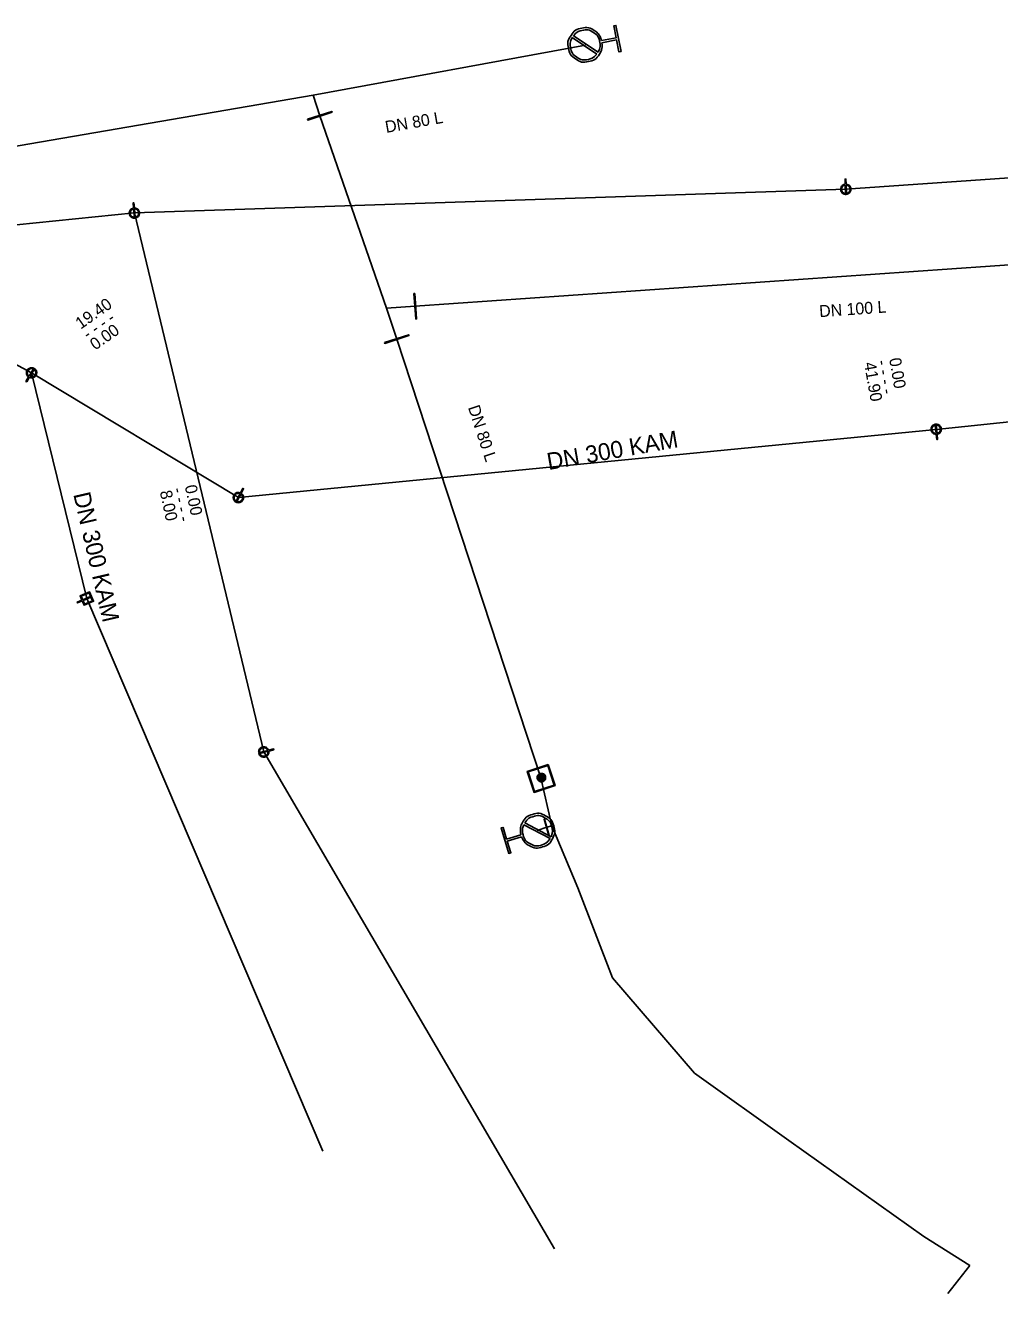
# Model space of a CAD drawing. Extents: x -818321 to -817653, y -1049725 to -1049329.
# Drawn here: x -817918.3 to -817861, y -1049467.6 to -1049393 of the extents above; entities that cross this region are included whole.
import ezdxf

# ---------------------------------------------------------------- set-up
doc = ezdxf.new("R2010")
doc.units = 0
doc.layers.add('Default', color=7, linetype='Continuous')
doc.layers.add('Level 0', color=7, linetype='Continuous')

msp = doc.modelspace()

# ---------------------------------------------------------------- linework, layer by layer
at = {"layer": 'Default'}
for points in [[(-817886.035, -1049393.634), (-817884.588, -1049394.608)], [(-817884.382, -1049393.921), (-817883.519, -1049393.754), (-817883.656, -1049393.048), (-817883.533, -1049393.024), (-817883.235, -1049394.558), (-817883.358, -1049394.582), (-817883.495, -1049393.876), (-817884.358, -1049394.044)], [(-817884.659, -1049394.714), (-817886.107, -1049393.737)], [(-817901.679, -1049398.548), (-817900.252, -1049398.085), (-817900.238, -1049398.129), (-817901.664, -1049398.593), (-817901.679, -1049398.548)], [(-817870.046, -1049402.367), (-817870.056, -1049402.066), (-817870.007, -1049402.065), (-817869.997, -1049402.365)], [(-817870.027, -1049402.915), (-817870.044, -1049402.418)], [(-817869.995, -1049402.416), (-817869.978, -1049402.913)], [(-817911.914, -1049403.77), (-817911.94, -1049403.471), (-817911.891, -1049403.466), (-817911.865, -1049403.766)], [(-817911.866, -1049404.316), (-817911.91, -1049403.821)], [(-817911.861, -1049403.817), (-817911.817, -1049404.312)], [(-817895.369, -1049408.795), (-817895.264, -1049410.291), (-817895.311, -1049410.294), (-817895.416, -1049408.798), (-817895.369, -1049408.795)], [(-817897.154, -1049411.687), (-817895.727, -1049411.223), (-817895.712, -1049411.268), (-817897.139, -1049411.731), (-817897.154, -1049411.687)], [(-817918.047, -1049413.732), (-817918.202, -1049413.99), (-817918.244, -1049413.964), (-817918.09, -1049413.707)], [(-817918.063, -1049413.663), (-817917.807, -1049413.236)], [(-817917.765, -1049413.262), (-817918.021, -1049413.688)], [(-817864.694, -1049417.033), (-817864.746, -1049416.539)], [(-817864.697, -1049416.534), (-817864.645, -1049417.028)], [(-817864.64, -1049417.079), (-817864.608, -1049417.378), (-817864.657, -1049417.383), (-817864.689, -1049417.084)], [(-817905.628, -1049420.524), (-817905.486, -1049420.258), (-817905.443, -1049420.281), (-817905.584, -1049420.547)], [(-817905.885, -1049421.008), (-817905.652, -1049420.569)], [(-817905.608, -1049420.592), (-817905.842, -1049421.031)], [(-817914.929, -1049426.879), (-817915.205, -1049426.996), (-817915.225, -1049426.951), (-817914.949, -1049426.834), (-817915.056, -1049426.58), (-817914.504, -1049426.346), (-817914.269, -1049426.898), (-817914.822, -1049427.133), (-817914.929, -1049426.879)], [(-817914.903, -1049426.815), (-817914.442, -1049426.619), (-817914.53, -1049426.41), (-817914.992, -1049426.606), (-817914.903, -1049426.815)], [(-817914.884, -1049426.86), (-817914.796, -1049427.068), (-817914.334, -1049426.872), (-817914.422, -1049426.664), (-817914.884, -1049426.86)], [(-817904.501, -1049435.803), (-817904.02, -1049435.674)], [(-817904.008, -1049435.722), (-817904.488, -1049435.851)], [(-817903.971, -1049435.661), (-817903.681, -1049435.583), (-817903.668, -1049435.631), (-817903.958, -1049435.709)], [(-817887.518, -1049436.507), (-817887.116, -1049437.743), (-817888.353, -1049438.145), (-817888.754, -1049436.908), (-817887.518, -1049436.507)], [(-817888.703, -1049436.934), (-817888.327, -1049438.094), (-817887.167, -1049437.717), (-817887.544, -1049436.558), (-817888.703, -1049436.934)], [(-817888.894, -1049439.931), (-817887.353, -1049440.751)], [(-817887.733, -1049439.709), (-817887.457, -1049440.67), (-817887.487, -1049440.679), (-817887.763, -1049439.718), (-817887.733, -1049439.709)], [(-817889.088, -1049440.748), (-817889.928, -1049441.005), (-817889.718, -1049441.692), (-817889.838, -1049441.729), (-817890.295, -1049440.235), (-817890.175, -1049440.198), (-817889.965, -1049440.886), (-817889.124, -1049440.629)], [(-817887.413, -1049440.861), (-817888.954, -1049440.043)]]:
    msp.add_lwpolyline(points, dxfattribs=at)
for points in [[(-817884.358, -1049394.044), (-817884.312, -1049394.431), (-817884.518, -1049394.734), (-817884.75, -1049395.076), (-817885.159, -1049395.155), (-817885.565, -1049395.234), (-817885.908, -1049395.002), (-817886.25, -1049394.77), (-817886.329, -1049394.362), (-817886.408, -1049393.957), (-817886.177, -1049393.614), (-817885.947, -1049393.271), (-817885.54, -1049393.192), (-817885.132, -1049393.112), (-817884.789, -1049393.342), (-817884.483, -1049393.545), (-817884.382, -1049393.921)], [(-817884.588, -1049394.608), (-817884.426, -1049394.33), (-817884.489, -1049394.004), (-817884.558, -1049393.647), (-817884.857, -1049393.446), (-817885.156, -1049393.244), (-817885.512, -1049393.314), (-817885.838, -1049393.377), (-817886.035, -1049393.634)], [(-817886.107, -1049393.737), (-817886.266, -1049394.013), (-817886.207, -1049394.338), (-817886.134, -1049394.692), (-817885.835, -1049394.894), (-817885.536, -1049395.097), (-817885.179, -1049395.028), (-817884.855, -1049394.965), (-817884.659, -1049394.714)], [(-817869.997, -1049402.365), (-817869.934, -1049402.367), (-817869.871, -1049402.4), (-817869.798, -1049402.437), (-817869.756, -1049402.507), (-817869.714, -1049402.577), (-817869.711, -1049402.655), (-817869.708, -1049402.733), (-817869.746, -1049402.807), (-817869.784, -1049402.88), (-817869.854, -1049402.921), (-817869.924, -1049402.962), (-817870, -1049402.965), (-817870.076, -1049402.968), (-817870.149, -1049402.932), (-817870.222, -1049402.895), (-817870.265, -1049402.825), (-817870.308, -1049402.754), (-817870.311, -1049402.676), (-817870.313, -1049402.598), (-817870.276, -1049402.525), (-817870.239, -1049402.452), (-817870.169, -1049402.41), (-817870.108, -1049402.373), (-817870.046, -1049402.367)], [(-817870.044, -1049402.418), (-817870.093, -1049402.423), (-817870.144, -1049402.454), (-817870.202, -1049402.488), (-817870.232, -1049402.549), (-817870.263, -1049402.609), (-817870.261, -1049402.674), (-817870.259, -1049402.739), (-817870.223, -1049402.798), (-817870.187, -1049402.857), (-817870.126, -1049402.887), (-817870.074, -1049402.913), (-817870.027, -1049402.915)], [(-817869.978, -1049402.913), (-817869.93, -1049402.907), (-817869.88, -1049402.878), (-817869.821, -1049402.844), (-817869.79, -1049402.783), (-817869.759, -1049402.721), (-817869.761, -1049402.656), (-817869.763, -1049402.591), (-817869.798, -1049402.533), (-817869.833, -1049402.475), (-817869.894, -1049402.445), (-817869.946, -1049402.418), (-817869.995, -1049402.416)], [(-817911.865, -1049403.766), (-817911.803, -1049403.764), (-817911.737, -1049403.794), (-817911.663, -1049403.827), (-817911.617, -1049403.895), (-817911.571, -1049403.962), (-817911.565, -1049404.04), (-817911.558, -1049404.118), (-817911.592, -1049404.194), (-817911.626, -1049404.269), (-817911.694, -1049404.314), (-817911.762, -1049404.358), (-817911.837, -1049404.365), (-817911.913, -1049404.372), (-817911.988, -1049404.339), (-817912.062, -1049404.307), (-817912.109, -1049404.239), (-817912.156, -1049404.171), (-817912.162, -1049404.092), (-817912.169, -1049404.015), (-817912.136, -1049403.94), (-817912.103, -1049403.865), (-817912.035, -1049403.82), (-817911.976, -1049403.78), (-817911.914, -1049403.77)], [(-817911.91, -1049403.821), (-817911.958, -1049403.829), (-817912.007, -1049403.862), (-817912.063, -1049403.9), (-817912.091, -1049403.961), (-817912.118, -1049404.023), (-817912.113, -1049404.088), (-817912.107, -1049404.153), (-817912.068, -1049404.21), (-817912.03, -1049404.267), (-817911.967, -1049404.293), (-817911.914, -1049404.316), (-817911.866, -1049404.316)], [(-817911.817, -1049404.312), (-817911.77, -1049404.304), (-817911.721, -1049404.272), (-817911.665, -1049404.235), (-817911.637, -1049404.172), (-817911.609, -1049404.109), (-817911.614, -1049404.044), (-817911.62, -1049403.98), (-817911.658, -1049403.924), (-817911.696, -1049403.867), (-817911.758, -1049403.84), (-817911.811, -1049403.816), (-817911.861, -1049403.817)], [(-817918.09, -1049413.707), (-817918.141, -1049413.671), (-817918.176, -1049413.609), (-817918.217, -1049413.538), (-817918.215, -1049413.456), (-817918.212, -1049413.375), (-817918.171, -1049413.308), (-817918.131, -1049413.241), (-817918.059, -1049413.2), (-817917.987, -1049413.159), (-817917.906, -1049413.162), (-817917.825, -1049413.166), (-817917.76, -1049413.205), (-817917.695, -1049413.244), (-817917.653, -1049413.314), (-817917.612, -1049413.385), (-817917.614, -1049413.467), (-817917.617, -1049413.55), (-817917.657, -1049413.617), (-817917.697, -1049413.684), (-817917.768, -1049413.725), (-817917.839, -1049413.766), (-817917.92, -1049413.762), (-817917.992, -1049413.76), (-817918.047, -1049413.732)], [(-817917.807, -1049413.236), (-817917.85, -1049413.215), (-817917.908, -1049413.213), (-817917.976, -1049413.209), (-817918.036, -1049413.244), (-817918.095, -1049413.278), (-817918.129, -1049413.334), (-817918.162, -1049413.389), (-817918.165, -1049413.457), (-817918.167, -1049413.525), (-817918.133, -1049413.584), (-817918.104, -1049413.634), (-817918.063, -1049413.663)], [(-817918.021, -1049413.688), (-817917.977, -1049413.71), (-817917.918, -1049413.712), (-817917.851, -1049413.715), (-817917.792, -1049413.681), (-817917.733, -1049413.647), (-817917.7, -1049413.591), (-817917.666, -1049413.536), (-817917.664, -1049413.467), (-817917.662, -1049413.398), (-817917.697, -1049413.34), (-817917.726, -1049413.29), (-817917.765, -1049413.262)], [(-817864.689, -1049417.084), (-817864.751, -1049417.087), (-817864.817, -1049417.058), (-817864.892, -1049417.027), (-817864.939, -1049416.96), (-817864.986, -1049416.893), (-817864.994, -1049416.815), (-817865.002, -1049416.737), (-817864.969, -1049416.661), (-817864.937, -1049416.585), (-817864.87, -1049416.539), (-817864.803, -1049416.493), (-817864.727, -1049416.485), (-817864.652, -1049416.478), (-817864.576, -1049416.509), (-817864.501, -1049416.539), (-817864.453, -1049416.607), (-817864.405, -1049416.674), (-817864.397, -1049416.752), (-817864.389, -1049416.83), (-817864.421, -1049416.905), (-817864.453, -1049416.98), (-817864.52, -1049417.027), (-817864.578, -1049417.068), (-817864.64, -1049417.079)], [(-817864.746, -1049416.539), (-817864.793, -1049416.548), (-817864.841, -1049416.581), (-817864.897, -1049416.619), (-817864.924, -1049416.682), (-817864.951, -1049416.745), (-817864.944, -1049416.81), (-817864.938, -1049416.875), (-817864.899, -1049416.93), (-817864.86, -1049416.985), (-817864.797, -1049417.012), (-817864.743, -1049417.035), (-817864.694, -1049417.033)], [(-817864.645, -1049417.028), (-817864.597, -1049417.02), (-817864.548, -1049416.986), (-817864.493, -1049416.947), (-817864.466, -1049416.885), (-817864.44, -1049416.822), (-817864.447, -1049416.758), (-817864.454, -1049416.693), (-817864.493, -1049416.637), (-817864.533, -1049416.581), (-817864.596, -1049416.555), (-817864.649, -1049416.533), (-817864.697, -1049416.534)], [(-817905.584, -1049420.547), (-817905.531, -1049420.58), (-817905.492, -1049420.64), (-817905.448, -1049420.708), (-817905.446, -1049420.79), (-817905.445, -1049420.872), (-817905.482, -1049420.94), (-817905.518, -1049421.01), (-817905.588, -1049421.054), (-817905.657, -1049421.099), (-817905.739, -1049421.1), (-817905.82, -1049421.1), (-817905.887, -1049421.064), (-817905.954, -1049421.029), (-817905.999, -1049420.961), (-817906.044, -1049420.893), (-817906.046, -1049420.811), (-817906.048, -1049420.728), (-817906.011, -1049420.659), (-817905.975, -1049420.59), (-817905.906, -1049420.545), (-817905.838, -1049420.501), (-817905.756, -1049420.5), (-817905.684, -1049420.498), (-817905.628, -1049420.524)], [(-817905.652, -1049420.569), (-817905.697, -1049420.549), (-817905.756, -1049420.55), (-817905.823, -1049420.551), (-817905.88, -1049420.588), (-817905.937, -1049420.625), (-817905.967, -1049420.682), (-817905.998, -1049420.74), (-817905.996, -1049420.808), (-817905.995, -1049420.877), (-817905.957, -1049420.934), (-817905.925, -1049420.982), (-817905.885, -1049421.008)], [(-817905.842, -1049421.031), (-817905.798, -1049421.05), (-817905.739, -1049421.05), (-817905.671, -1049421.049), (-817905.614, -1049421.012), (-817905.556, -1049420.974), (-817905.526, -1049420.917), (-817905.495, -1049420.86), (-817905.496, -1049420.792), (-817905.497, -1049420.724), (-817905.535, -1049420.667), (-817905.566, -1049420.618), (-817905.608, -1049420.592)], [(-817903.958, -1049435.709), (-817903.946, -1049435.77), (-817903.964, -1049435.839), (-817903.983, -1049435.919), (-817904.042, -1049435.975), (-817904.101, -1049436.032), (-817904.176, -1049436.052), (-817904.252, -1049436.072), (-817904.332, -1049436.052), (-817904.412, -1049436.032), (-817904.468, -1049435.973), (-817904.524, -1049435.914), (-817904.544, -1049435.84), (-817904.563, -1049435.767), (-817904.545, -1049435.688), (-817904.526, -1049435.608), (-817904.467, -1049435.551), (-817904.408, -1049435.493), (-817904.332, -1049435.473), (-817904.256, -1049435.452), (-817904.177, -1049435.472), (-817904.098, -1049435.492), (-817904.041, -1049435.551), (-817903.991, -1049435.602), (-817903.971, -1049435.661)], [(-817904.02, -1049435.674), (-817904.037, -1049435.628), (-817904.078, -1049435.585), (-817904.125, -1049435.537), (-817904.19, -1049435.52), (-817904.256, -1049435.504), (-817904.319, -1049435.521), (-817904.382, -1049435.538), (-817904.431, -1049435.586), (-817904.48, -1049435.634), (-817904.496, -1049435.7), (-817904.509, -1049435.756), (-817904.501, -1049435.803)], [(-817904.488, -1049435.851), (-817904.472, -1049435.895), (-817904.432, -1049435.938), (-817904.385, -1049435.987), (-817904.319, -1049436.004), (-817904.252, -1049436.021), (-817904.189, -1049436.004), (-817904.126, -1049435.987), (-817904.078, -1049435.94), (-817904.029, -1049435.893), (-817904.013, -1049435.827), (-817903.998, -1049435.77), (-817904.008, -1049435.722)], [(-817887.92, -1049437.021), (-817887.857, -1049437.021), (-817887.797, -1049437.054), (-817887.737, -1049437.086), (-817887.703, -1049437.146), (-817887.669, -1049437.206), (-817887.669, -1049437.272), (-817887.669, -1049437.337), (-817887.702, -1049437.396), (-817887.735, -1049437.455), (-817887.795, -1049437.488), (-817887.854, -1049437.521), (-817887.92, -1049437.521), (-817887.984, -1049437.521), (-817888.044, -1049437.488), (-817888.103, -1049437.455), (-817888.136, -1049437.396), (-817888.169, -1049437.337), (-817888.169, -1049437.272), (-817888.169, -1049437.206), (-817888.136, -1049437.146), (-817888.102, -1049437.086), (-817888.042, -1049437.054), (-817887.983, -1049437.021), (-817887.92, -1049437.021)], [(-817887.92, -1049437.045), (-817887.977, -1049437.045), (-817888.031, -1049437.074), (-817888.085, -1049437.103), (-817888.115, -1049437.158), (-817888.146, -1049437.212), (-817888.146, -1049437.272), (-817888.146, -1049437.33), (-817888.116, -1049437.384), (-817888.086, -1049437.438), (-817888.032, -1049437.468), (-817887.978, -1049437.498), (-817887.92, -1049437.498), (-817887.86, -1049437.498), (-817887.806, -1049437.468), (-817887.752, -1049437.438), (-817887.723, -1049437.384), (-817887.693, -1049437.33), (-817887.693, -1049437.272), (-817887.693, -1049437.212), (-817887.723, -1049437.158), (-817887.754, -1049437.103), (-817887.808, -1049437.074), (-817887.862, -1049437.045), (-817887.92, -1049437.045)], [(-817887.92, -1049437.062), (-817887.867, -1049437.062), (-817887.817, -1049437.089), (-817887.767, -1049437.116), (-817887.738, -1049437.166), (-817887.71, -1049437.217), (-817887.71, -1049437.272), (-817887.71, -1049437.326), (-817887.737, -1049437.376), (-817887.765, -1049437.426), (-817887.815, -1049437.453), (-817887.865, -1049437.481), (-817887.92, -1049437.481), (-817887.974, -1049437.481), (-817888.024, -1049437.453), (-817888.074, -1049437.426), (-817888.101, -1049437.376), (-817888.129, -1049437.326), (-817888.129, -1049437.272), (-817888.129, -1049437.217), (-817888.101, -1049437.166), (-817888.073, -1049437.116), (-817888.022, -1049437.089), (-817887.972, -1049437.062), (-817887.92, -1049437.062)], [(-817887.92, -1049437.084), (-817887.998, -1049437.084), (-817888.052, -1049437.139), (-817888.107, -1049437.194), (-817888.107, -1049437.272), (-817888.107, -1049437.349), (-817888.052, -1049437.404), (-817887.997, -1049437.459), (-817887.92, -1049437.459), (-817887.842, -1049437.459), (-817887.787, -1049437.404), (-817887.732, -1049437.349), (-817887.732, -1049437.272), (-817887.732, -1049437.194), (-817887.786, -1049437.139), (-817887.841, -1049437.084), (-817887.92, -1049437.084)], [(-817887.92, -1049437.107), (-817887.851, -1049437.107), (-817887.803, -1049437.155), (-817887.756, -1049437.203), (-817887.756, -1049437.271), (-817887.756, -1049437.339), (-817887.804, -1049437.387), (-817887.852, -1049437.435), (-817887.92, -1049437.435), (-817887.988, -1049437.435), (-817888.036, -1049437.387), (-817888.084, -1049437.339), (-817888.084, -1049437.271), (-817888.084, -1049437.203), (-817888.036, -1049437.155), (-817887.988, -1049437.107), (-817887.92, -1049437.107)], [(-817887.92, -1049437.127), (-817887.98, -1049437.127), (-817888.022, -1049437.169), (-817888.064, -1049437.211), (-817888.064, -1049437.271), (-817888.064, -1049437.331), (-817888.022, -1049437.373), (-817887.98, -1049437.415), (-817887.92, -1049437.415), (-817887.86, -1049437.415), (-817887.818, -1049437.373), (-817887.775, -1049437.331), (-817887.775, -1049437.271), (-817887.775, -1049437.211), (-817887.817, -1049437.169), (-817887.859, -1049437.127), (-817887.92, -1049437.127)], [(-817887.92, -1049437.146), (-817887.867, -1049437.146), (-817887.831, -1049437.183), (-817887.794, -1049437.22), (-817887.794, -1049437.272), (-817887.794, -1049437.323), (-817887.831, -1049437.36), (-817887.868, -1049437.396), (-817887.92, -1049437.396), (-817887.971, -1049437.396), (-817888.008, -1049437.36), (-817888.044, -1049437.323), (-817888.044, -1049437.272), (-817888.044, -1049437.22), (-817888.008, -1049437.183), (-817887.972, -1049437.146), (-817887.92, -1049437.146)], [(-817887.92, -1049437.17), (-817887.962, -1049437.17), (-817887.991, -1049437.199), (-817888.021, -1049437.229), (-817888.021, -1049437.271), (-817888.021, -1049437.313), (-817887.991, -1049437.343), (-817887.962, -1049437.373), (-817887.92, -1049437.373), (-817887.878, -1049437.373), (-817887.848, -1049437.343), (-817887.818, -1049437.313), (-817887.818, -1049437.271), (-817887.818, -1049437.229), (-817887.848, -1049437.199), (-817887.877, -1049437.17), (-817887.92, -1049437.17)], [(-817887.92, -1049437.187), (-817887.884, -1049437.187), (-817887.86, -1049437.211), (-817887.835, -1049437.236), (-817887.835, -1049437.271), (-817887.835, -1049437.306), (-817887.86, -1049437.331), (-817887.885, -1049437.355), (-817887.92, -1049437.355), (-817887.955, -1049437.355), (-817887.979, -1049437.331), (-817888.004, -1049437.306), (-817888.004, -1049437.271), (-817888.004, -1049437.236), (-817887.979, -1049437.211), (-817887.955, -1049437.187), (-817887.92, -1049437.187)], [(-817887.92, -1049437.209), (-817887.945, -1049437.209), (-817887.964, -1049437.227), (-817887.982, -1049437.245), (-817887.982, -1049437.271), (-817887.982, -1049437.297), (-817887.963, -1049437.316), (-817887.945, -1049437.334), (-817887.92, -1049437.334), (-817887.893, -1049437.334), (-817887.875, -1049437.316), (-817887.857, -1049437.297), (-817887.857, -1049437.271), (-817887.857, -1049437.245), (-817887.875, -1049437.227), (-817887.893, -1049437.209), (-817887.92, -1049437.209)], [(-817887.92, -1049437.232), (-817887.903, -1049437.232), (-817887.892, -1049437.243), (-817887.88, -1049437.255), (-817887.88, -1049437.271), (-817887.88, -1049437.287), (-817887.892, -1049437.299), (-817887.903, -1049437.31), (-817887.92, -1049437.31), (-817887.936, -1049437.31), (-817887.947, -1049437.299), (-817887.959, -1049437.287), (-817887.959, -1049437.271), (-817887.959, -1049437.255), (-817887.947, -1049437.243), (-817887.936, -1049437.232), (-817887.92, -1049437.232)], [(-817887.92, -1049437.248), (-817887.929, -1049437.248), (-817887.936, -1049437.255), (-817887.943, -1049437.261), (-817887.943, -1049437.271), (-817887.943, -1049437.281), (-817887.936, -1049437.288), (-817887.929, -1049437.295), (-817887.92, -1049437.295), (-817887.91, -1049437.295), (-817887.903, -1049437.288), (-817887.896, -1049437.281), (-817887.896, -1049437.271), (-817887.896, -1049437.261), (-817887.903, -1049437.255), (-817887.91, -1049437.248), (-817887.92, -1049437.248)], [(-817889.124, -1049440.629), (-817889.21, -1049440.248), (-817889.037, -1049439.926), (-817888.842, -1049439.562), (-817888.444, -1049439.44), (-817888.048, -1049439.319), (-817887.683, -1049439.514), (-817887.318, -1049439.709), (-817887.197, -1049440.107), (-817887.076, -1049440.501), (-817887.27, -1049440.866), (-817887.463, -1049441.232), (-817887.859, -1049441.353), (-817888.257, -1049441.474), (-817888.622, -1049441.282), (-817888.948, -1049441.112), (-817889.088, -1049440.748)], [(-817887.353, -1049440.751), (-817887.223, -1049440.46), (-817887.316, -1049440.143), (-817887.426, -1049439.799), (-817887.744, -1049439.629), (-817888.063, -1049439.458), (-817888.41, -1049439.565), (-817888.726, -1049439.661), (-817888.894, -1049439.931)], [(-817888.954, -1049440.043), (-817889.087, -1049440.337), (-817888.99, -1049440.655), (-817888.883, -1049441.002), (-817888.565, -1049441.171), (-817888.247, -1049441.341), (-817887.9, -1049441.234), (-817887.582, -1049441.137), (-817887.413, -1049440.861)]]:
    msp.add_open_spline(points, degree=3, dxfattribs=at)
at = {"layer": 'Level 0'}
for p, q in [((-817901.349, -1049397.13), (-817885.334, -1049394.18)), ((-817927.943, -1049401.705), (-817901.349, -1049397.13)), ((-817901.349, -1049397.13), (-817900.958, -1049398.339)), ((-817900.958, -1049398.339), (-817897.038, -1049409.663)), ((-817834.018, -1049400.128), (-817870.011, -1049402.66)), ((-817870.011, -1049402.66), (-817911.864, -1049404.061)), ((-817911.864, -1049404.061), (-817941.902, -1049407.077)), ((-817917.917, -1049413.467), (-817935.43, -1049404)), ((-817904.249, -1049435.761), (-817911.864, -1049404.061)), ((-817895.341, -1049409.545), (-817833.169, -1049405.216)), ((-817897.038, -1049409.663), (-817895.341, -1049409.545)), ((-817897.038, -1049409.663), (-817896.433, -1049411.478)), ((-817896.433, -1049411.478), (-817887.953, -1049437.285)), ((-817905.744, -1049420.795), (-817917.917, -1049413.467)), ((-817914.671, -1049426.745), (-817917.917, -1049413.467)), ((-817830.553, -1049413.282), (-817864.695, -1049416.789)), ((-817864.695, -1049416.789), (-817905.744, -1049420.795)), ((-817900.773, -1049459.247), (-817914.671, -1049426.745)), ((-817887.142, -1049464.999), (-817904.249, -1049435.761)), ((-817887.953, -1049437.285), (-817887.298, -1049440.112)), ((-817888.167, -1049440.392), (-817887.61, -1049440.194)), ((-817887.61, -1049440.194), (-817887.298, -1049440.112)), ((-817887.298, -1049440.112), (-817885.779, -1049443.76)), ((-817885.779, -1049443.76), (-817883.743, -1049449.042)), ((-817883.743, -1049449.042), (-817878.918, -1049454.664)), ((-817878.918, -1049454.664), (-817873.367, -1049458.611)), ((-817873.367, -1049458.611), (-817865.424, -1049464.257)), ((-817865.424, -1049464.257), (-817862.715, -1049465.961)), ((-817862.715, -1049465.961), (-817864, -1049467.625))]:
    msp.add_line(p, q, dxfattribs=at)

# ---------------------------------------------------------------- texts
for s, height, rotation, p in [('DN 80 L', 0.7, 10, (-817897.049, -1049399.353)), ('19.40', 0.7, 35, (-817915.027, -1049410.926)), ('DN 100 L', 0.7, 4, (-817871.552, -1049410.191)), ('- - - -', 0.7, 35, (-817914.599, -1049411.542)), ('0.00', 0.7, 35, (-817914.17, -1049412.157)), ('41.90', 0.7, 280, (-817868.946, -1049412.89)), ('- - - -', 0.7, 280, (-817868.207, -1049412.765)), ('0.00', 0.7, 280, (-817867.467, -1049412.641)), ('DN 80 L', 0.7, 288, (-817892.246, -1049415.493)), ('DN 300 KAM', 1, 10, (-817887.502, -1049419.184)), ('DN 300 KAM', 1, 283, (-817915.466, -1049420.6)), ('8.00', 0.7, 282, (-817910.371, -1049420.449)), ('- - - -', 0.7, 282, (-817909.639, -1049420.287)), ('0.00', 0.7, 282, (-817908.906, -1049420.126))]:
    msp.add_text(s, height=height, rotation=rotation, dxfattribs=at).set_placement(p)

doc.saveas('drawing.dxf')
